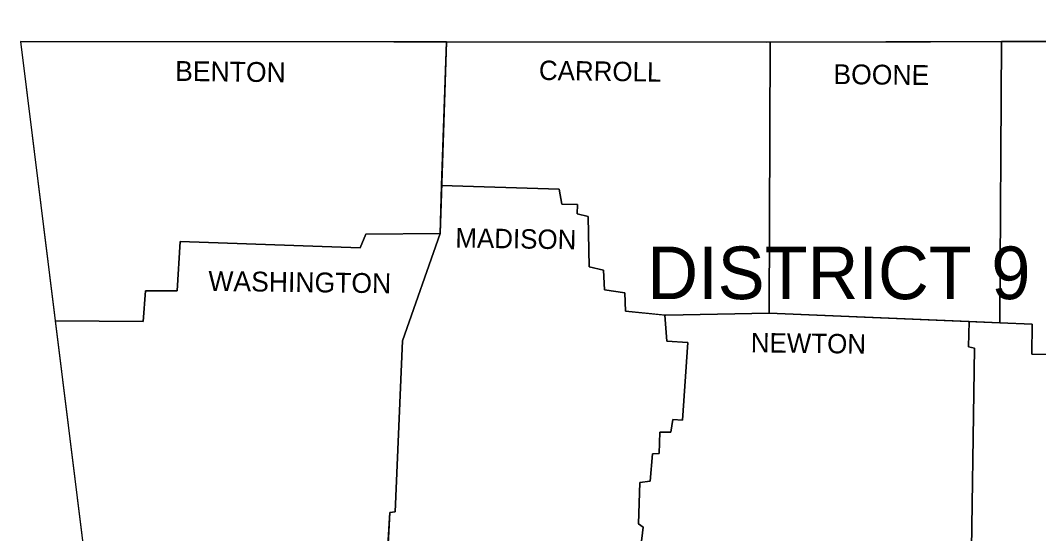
# Model space of a CAD drawing. Extents: x -28335 to 1228743, y -22428 to 152440.
# Drawn here: x 23987 to 28984, y 15169 to 17688 of the extents above; entities that cross this region are included whole.
import ezdxf

# ---------------------------------------------------------------- set-up
doc = ezdxf.new("R2010")
doc.units = 0
doc.layers.add('Level 16', color=7, linetype='Continuous')
doc.layers.add('Level 8', color=7, linetype='Continuous')

msp = doc.modelspace()

# ---------------------------------------------------------------- linework, layer by layer
at = {"layer": 'Level 16'}
for p, q in [((26078.5, 17582.4), (23987.2, 17583.7)), ((23987.2, 17583.7), (24157.9, 16213.3)), ((26078.5, 17582.4), (26054.5, 16877.6)), ((27650.2, 17581.4), (26078.5, 17582.4)), ((27666.2, 17581.5), (27650.2, 17581.4)), ((27666.2, 17581.5), (27661.6, 16251.7)), ((28801.1, 17583.9), (27666.2, 17581.5)), ((28794.2, 16204), (28801.1, 17583.9)), ((28801.1, 17583.9), (28794.2, 16204)), ((29797.9, 17586), (28801.1, 17583.9)), ((26054.5, 16877.6), (26046.4, 16641.3)), ((26630.8, 16858.8), (26054.5, 16877.6)), ((26644.4, 16786.3), (26630.8, 16858.8)), ((26773.6, 16725.2), (26719.2, 16738.8)), ((26778.1, 16478.2), (26773.6, 16725.2)), ((25681.7, 16639.1), (25654.5, 16571.1)), ((26046.4, 16641.3), (25681.7, 16639.1)), ((24771, 16602.8), (24757.4, 16360.5)), ((25654.5, 16571.1), (24771, 16602.8)), ((26848.3, 16462.4), (26778.1, 16478.2)), ((24757.4, 16360.5), (24601.1, 16360.5)), ((27149.2, 16240.9), (26957, 16260.8)), ((27154.1, 16240.4), (27149.2, 16240.9)), ((27661.6, 16251.7), (27154.1, 16240.4)), ((27661.6, 16251.7), (28794.2, 16204)), ((28642.5, 16210.4), (27661.6, 16251.7)), ((24157.9, 16213.3), (24306.8, 15017.6)), ((27027.3, 15420.4), (27077.1, 15427.2)), ((25786.3, 15026.5), (25799.5, 15273.1)), ((25799.5, 15273.1), (25826.7, 15275.4))]:
    msp.add_line(p, q, dxfattribs=at)
for points in [[(26046.4, 16641.3), (26054.5, 16877.6), (26078.5, 17582.4)], [(26054.5, 16877.6), (26630.8, 16858.8), (26644.4, 16786.3), (26721.5, 16784.1), (26719.2, 16738.8), (26773.6, 16725.2), (26778.1, 16478.2), (26848.3, 16462.4), (26852.8, 16365), (26952.5, 16351.4), (26957, 16260.8), (27154.1, 16240.4), (27661.6, 16251.7), (27666.2, 17581.5)], [(26719.2, 16738.8), (26721.5, 16784.1), (26644.4, 16786.3)], [(24157.9, 16213.3), (24589.8, 16210.9), (24601.1, 16360.5), (24757.4, 16360.5), (24771, 16602.8), (25654.5, 16571.1), (25681.7, 16639.1), (26046.4, 16641.3)], [(26046.4, 16641.3), (25862.9, 16115.8), (25826.7, 15275.4), (25799.5, 15273.1), (25786.3, 15026.5), (25785.9, 15019.4), (25919.5, 15008.1), (25939.9, 15028.5), (26544.8, 15017.1)], [(25826.7, 15275.4), (25862.9, 16115.8), (26046.4, 16641.3)], [(26957, 16260.8), (26952.5, 16351.4), (26852.8, 16365), (26848.3, 16462.4)], [(24601.1, 16360.5), (24589.8, 16210.9), (24157.9, 16213.3)], [(27149.2, 16240.9), (27158.7, 16113.5), (27262.9, 16106.7), (27235.7, 15726.2), (27188.1, 15728.5), (27179, 15667.3), (27124.7, 15667.3), (27122.4, 15563.1), (27088.4, 15560.8), (27077.1, 15427.2), (27027.3, 15420.4), (27020.5, 15216.5), (27043.1, 15200.6), (27020.5, 15008.1)], [(27235.7, 15726.2), (27262.9, 16106.7), (27158.7, 16113.5), (27149.2, 16240.9)], [(28651.4, 14874.9), (28669.6, 16079.6), (28640.2, 16086.4), (28642.5, 16210.4)], [(28642.5, 16210.4), (28640.2, 16086.4), (28669.6, 16079.6), (28651.4, 14874.9)], [(30140.8, 16041), (28950.5, 16050.1), (28952.8, 16197.4), (28794.2, 16204), (28642.5, 16210.4)], [(28794.2, 16204), (28952.8, 16197.4), (28950.5, 16050.1), (30140.8, 16041)], [(27179, 15667.3), (27188.1, 15728.5), (27235.7, 15726.2)], [(27077.1, 15427.2), (27088.4, 15560.8), (27122.4, 15563.1), (27124.7, 15667.3), (27179, 15667.3)], [(27020.5, 15008.1), (27043.1, 15200.6), (27020.5, 15216.5), (27027.3, 15420.4)]]:
    msp.add_lwpolyline(points, dxfattribs=at)
at = {"layer": 'Level 8'}
for points in [[(23987.2, 17583.7), (27650.2, 17581.4), (30864.7, 17588.2), (34656.8, 17647.1), (36414.7, 17687.9)], [(23987.2, 17583.7), (24456.1, 13818.8), (24252.3, 7673.2)], [(26078.5, 17582.4), (26046.4, 16641.3)], [(26054.5, 16877.6), (26630.8, 16858.8), (26644.4, 16786.3), (26721.5, 16784.1), (26719.2, 16738.8), (26773.6, 16725.2), (26778.1, 16478.2), (26848.3, 16462.4), (26852.8, 16365), (26952.5, 16351.4), (26957, 16260.8), (27154.1, 16240.4), (27661.6, 16251.7), (27666.2, 17581.5)], [(28801.1, 17583.9), (28794.2, 16204)], [(24157.9, 16213.3), (24589.8, 16210.9), (24601.1, 16360.5), (24757.4, 16360.5), (24771, 16602.8), (25654.5, 16571.1), (25681.7, 16639.1), (26046.4, 16641.3), (25862.9, 16115.8), (25826.7, 15275.4), (25799.5, 15273.1), (25785.9, 15019.4), (25919.5, 15008.1), (25939.9, 15028.5), (27020.5, 15008.1), (27031.8, 14888)], [(27149.2, 16240.9), (27158.7, 16113.5), (27262.9, 16106.7), (27235.7, 15726.2), (27188.1, 15728.5), (27179, 15667.3), (27124.7, 15667.3), (27122.4, 15563.1), (27088.4, 15560.8), (27077.1, 15427.2), (27027.3, 15420.4), (27020.5, 15216.5), (27043.1, 15200.6), (27020.5, 15008.1)], [(27661.6, 16251.7), (28952.8, 16197.4), (28950.5, 16050.1), (30140.8, 16041)], [(28642.5, 16210.4), (28640.2, 16086.4), (28669.6, 16079.6), (28651.4, 14874.9)]]:
    msp.add_lwpolyline(points, dxfattribs=at)

# ---------------------------------------------------------------- texts
for s, height, rotation, p in [('BENTON', 97.42, 359.2527, (24746.1, 17391.1)), ('CARROLL', 95.15, 359.1481, (26531.2, 17395.7)), ('BOONE', 97.42, 359.4001, (27976.4, 17375.3)), ('MADISON', 95.15, 359.0906, (26121.1, 16573.4)), ('WASHINGTON', 97.4, 359.232, (24909.2, 16360.5)), ('NEWTON', 95.15, 359.2717, (27570.9, 16059.2))]:
    msp.add_text(s, height=height, rotation=rotation, dxfattribs=at).set_placement(p)
msp.add_text('DISTRICT 9', height=258.24, dxfattribs=at).set_placement((27063.5, 16319.7))

doc.saveas('drawing.dxf')
